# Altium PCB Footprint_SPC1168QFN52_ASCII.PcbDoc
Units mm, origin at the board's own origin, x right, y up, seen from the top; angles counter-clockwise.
Board outline 152.4 x 101.6 mm, 2 copper layers (Top Layer, Bottom Layer); 1 components, 0 nets, 57 pads, 16 vias.
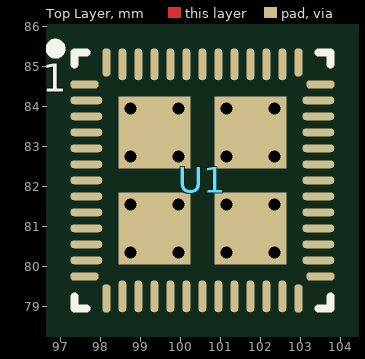
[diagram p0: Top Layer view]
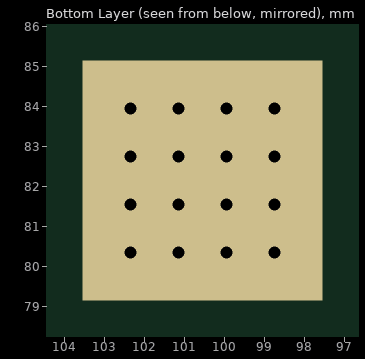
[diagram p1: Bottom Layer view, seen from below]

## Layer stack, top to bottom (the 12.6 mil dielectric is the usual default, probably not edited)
Top Solder: solder mask 0.0102, Solder Resist, Dk 3.5
Top Layer: signal copper 0.0356
Dielectric 1: dielectric 0.32, FR-4, Dk 4.8
Bottom Layer: signal copper 0.0356
Bottom Solder: solder mask 0.0102, Solder Resist, Dk 3.5

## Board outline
25.4,25.4 177.8,25.4 177.8,127 25.4,127

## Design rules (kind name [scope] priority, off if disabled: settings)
AssemblyTestPointUsage [All] p0: scope1count=1 scope1_0_kind=Board scope1_0_value=Board scope2count=1 scope2_0_kind=Board scope2_0_value=Board commentlength=0
AssemblyTestpoint [All] p0: scope1count=1 scope1_0_kind=Board scope1_0_value=Board scope2count=1 scope2_0_kind=Board scope2_0_value=Board commentlength=0
Clearance [All] p0: scope1count=1 scope1_0_kind=Board scope1_0_value=Board scope2count=1 scope2_0_kind=Board scope2_0_value=Board commentlength=0 gap=0.254
Clearance [All] p1: gap=0.254 ignorepadtopadclearanceinfootprint=FALSE except(0: Arc-Hole Track-Hole SMDPad-Hole THPad-Hole Via-Hole Fill-Hole Poly-Hole Region-Hole Text-Hole)
ComponentClearance [All] p0: scope1count=1 scope1_0_kind=Board scope1_0_value=Board scope2count=1 scope2_0_kind=Board scope2_0_value=Board commentlength=0 gap=0.254 collisioncheckmode=3
DiffPairsRouting [All] p0: scope1count=1 scope1_0_kind=Board scope1_0_value=Board scope2count=1 scope2_0_kind=Board scope2_0_value=Board commentlength=0
FabricationTestPointUsage [All] p0: scope1count=1 scope1_0_kind=Board scope1_0_value=Board scope2count=1 scope2_0_kind=Board scope2_0_value=Board commentlength=0 valid=0 allowmultiple=FALSE
FabricationTestpoint [All] p0: scope1count=1 scope1_0_kind=Board scope1_0_value=Board scope2count=1 scope2_0_kind=Board scope2_0_value=Board commentlength=0 side=3 testpointundercomponent=TRUE minsize=1.016 maxsize=2.54 preferedsize=1.524 minholesize=0 maxholesize=1.016 preferedholesize=0.813 testpointgrid=0.025
FanoutControl Fanout_BGA [All] p0 off: scope1count=1 scope1_0_kind=Board scope1_0_value=Board scope2count=1 scope2_0_kind=Board scope2_0_value=Board commentlength=69 // Protel DXP Scope 1 Expression Was: IsBGA   Fanout_BGA (Default Rule)
FanoutControl Fanout_LCC [All] p0 off: scope1count=1 scope1_0_kind=Board scope1_0_value=Board scope2count=1 scope2_0_kind=Board scope2_0_value=Board commentlength=69 // Protel DXP Scope 1 Expression Was: IsLCC   Fanout_LCC (Default Rule)
FanoutControl Fanout_SOIC [All] p0 off: scope1count=1 scope1_0_kind=Board scope1_0_value=Board scope2count=1 scope2_0_kind=Board scope2_0_value=Board commentlength=71 // Protel DXP Scope 1 Expression Was: IsSOIC   Fanout_SOIC (Default Rule)
FanoutControl Fanout_Small [All] p0 off: scope1count=1 scope1_0_kind=Board scope1_0_value=Board scope2count=1 scope2_0_kind=Board scope2_0_value=Board commentlength=84 // Protel DXP Scope 1 Expression Was: (CompPinCount < 5)   Fanout_Small (Default Rule)
FanoutControl Fanout_Default [All] p0: scope1count=1 scope1_0_kind=Board scope1_0_value=Board scope2count=1 scope2_0_kind=Board scope2_0_value=Board commentlength=30 // Fanout_Default (Default Rule)
Height [All] p0: scope1count=1 scope1_0_kind=Board scope1_0_value=Board scope2count=1 scope2_0_kind=Board scope2_0_value=Board commentlength=0
HoleSize [All] p0: scope1count=1 scope1_0_kind=Board scope1_0_value=Board scope2count=1 scope2_0_kind=Board scope2_0_value=Board commentlength=0 absolutevalues=TRUE maxlimit=2.54 minlimit=0.025 maxpercent=80.000 minpercent=20.000
HoleToHoleClearance [All] p0: scope1count=1 scope1_0_kind=Board scope1_0_value=Board scope2count=1 scope2_0_kind=Board scope2_0_value=Board commentlength=0
LayerPairs [All] p0: scope1count=1 scope1_0_kind=Board scope1_0_value=Board scope2count=1 scope2_0_kind=Board scope2_0_value=Board commentlength=0 enforce=TRUE
MinimumSolderMaskSliver [All] p0: scope1count=1 scope1_0_kind=Board scope1_0_value=Board scope2count=1 scope2_0_kind=Board scope2_0_value=Board commentlength=0
NetAntennae [All] p0: scope1count=1 scope1_0_kind=Board scope1_0_value=Board scope2count=1 scope2_0_kind=Board scope2_0_value=Board commentlength=0
PasteMaskExpansion [All] p0: scope1count=1 scope1_0_kind=Board scope1_0_value=Board scope2count=1 scope2_0_kind=Board scope2_0_value=Board commentlength=0 expansion=0
PlaneClearance [All] p0: scope1count=1 scope1_0_kind=Board scope1_0_value=Board scope2count=1 scope2_0_kind=Board scope2_0_value=Board commentlength=0 clearance=0.508
PlaneConnect [All] p0: scope1count=1 scope1_0_kind=Board scope1_0_value=Board scope2count=1 scope2_0_kind=Board scope2_0_value=Board commentlength=0 planeconnectstyle=Relief reliefexpansion=0.508 reliefentries=4 reliefconductorwidth=0.254 reliefairgap=0.254
PolygonConnect [All] p0: scope1count=1 scope1_0_kind=Board scope1_0_value=Board scope2count=1 scope2_0_kind=Board scope2_0_value=Board commentlength=0 connectstyle=Relief reliefconductorwidth=0.254 reliefentries=4 polygonreliefangle="90 Angle"
PolygonConnect [All] p1: connectstyle=Relief reliefconductorwidth=0.254 reliefentries=4 polygonreliefangle="90 Angle" airgapwidth=0.254
RoutingCorners [All] p0: scope1count=1 scope1_0_kind=Board scope1_0_value=Board scope2count=1 scope2_0_kind=Board scope2_0_value=Board commentlength=0 cornerstyle=45-Degree minsetback=2.54 maxsetback=2.54
RoutingLayers [All] p0: scope1count=1 scope1_0_kind=Board scope1_0_value=Board scope2count=1 scope2_0_kind=Board scope2_0_value=Board commentlength=0 top layer=Automatic bottom layer=Automatic
RoutingPriority [All] p0: scope1count=1 scope1_0_kind=Board scope1_0_value=Board scope2count=1 scope2_0_kind=Board scope2_0_value=Board commentlength=0
RoutingTopology [All] p0: scope1count=1 scope1_0_kind=Board scope1_0_value=Board scope2count=1 scope2_0_kind=Board scope2_0_value=Board commentlength=0 topology=Shortest
RoutingVias [All] p0: scope1count=1 scope1_0_kind=Board scope1_0_value=Board scope2count=1 scope2_0_kind=Board scope2_0_value=Board commentlength=0 holewidth=0.711 width=1.27 viastyle="Through Hole" minholewidth=0.711 minwidth=1.27 maxholewidth=0.711 maxwidth=1.27
RoutingVias [All] p1: holewidth=0.711 width=1.27 viastyle="Through Hole" minholewidth=0.711 minwidth=1.27 maxholewidth=0.711 maxwidth=1.27
ShortCircuit [All] p0: scope1count=1 scope1_0_kind=Board scope1_0_value=Board scope2count=1 scope2_0_kind=Board scope2_0_value=Board commentlength=0 allowed=FALSE
SilkToBoardRegionClearance [All] p0: scope1count=1 scope1_0_kind=Board scope1_0_value=Board scope2count=1 scope2_0_kind=Board scope2_0_value=Board commentlength=0
SilkToSilkClearance [All] p0: scope1count=1 scope1_0_kind=Board scope1_0_value=Board scope2count=1 scope2_0_kind=Board scope2_0_value=Board commentlength=0
SilkToSolderMaskClearance [All] p0 off: scope1count=1 scope1_0_kind=Board scope1_0_value=Board scope2count=1 scope2_0_kind=Board scope2_0_value=Board commentlength=44 // Protel DXP Scope 1 Expression Was: IsPad
SolderMaskExpansion [All] p0: scope1count=1 scope1_0_kind=Board scope1_0_value=Board scope2count=1 scope2_0_kind=Board scope2_0_value=Board commentlength=0 expansion=0.102
SolderMaskExpansion [All] p1: expansion=0.102 istentingtop=FALSE
UnRoutedNet [All] p0: scope1count=1 scope1_0_kind=Board scope1_0_value=Board scope2count=1 scope2_0_kind=Board scope2_0_value=Board commentlength=0
UnpouredPolygon [All] p0: scope1count=1 scope1_0_kind=Board scope1_0_value=Board scope2count=1 scope2_0_kind=Board scope2_0_value=Board commentlength=0
Width [All] p0: scope1count=1 scope1_0_kind=Board scope1_0_value=Board scope2count=1 scope2_0_kind=Board scope2_0_value=Board commentlength=0 maxlimit=0.254 minlimit=0.254 preferedwidth=0.254
Width [All] p1: maxlimit=0.254 minlimit=0.254 preferedwidth=0.254
30 further rules are at their usual default settings.

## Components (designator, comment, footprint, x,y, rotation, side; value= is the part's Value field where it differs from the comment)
U1 "" QFN-52-0.4 99.356,83.352 r0 top

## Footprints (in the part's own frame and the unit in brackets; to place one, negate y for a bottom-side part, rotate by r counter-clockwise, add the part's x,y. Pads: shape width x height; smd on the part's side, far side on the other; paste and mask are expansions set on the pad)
QFN-52-0.4 [mm] "P0.4,6*6mm"
  rect 1.8x1.8 smd: 0(0,-2.4) 0(0,0) 0(2.4,-2.4) 0(2.4,0)
  rect 6x6 smd far side: 0(1.2,-1.2)
  oct 0.7x0.2 smd: 1(-1.75,1.2) 13(-1.75,-3.6) 27(4.15,-3.6) 39(4.15,1.2)
  oval 0.8x0.2 smd: 2(-1.7,0.8) 3(-1.7,0.4) 4(-1.7,0) 5(-1.7,-0.4) 6(-1.7,-0.8) 7(-1.7,-1.2) 8(-1.7,-1.6) 9(-1.7,-2) 10(-1.7,-2.4) 11(-1.7,-2.8) 12(-1.7,-3.2) 28(4.1,-3.2) 29(4.1,-2.8) 30(4.1,-2.4) 31(4.1,-2) 32(4.1,-1.6) 33(4.1,-1.2) 34(4.1,-0.8) 35(4.1,-0.4) 36(4.1,0) 37(4.1,0.4) 38(4.1,0.8)
  oct 0.2x0.7 smd: 14(-1.2,-4.15) 26(3.6,-4.15) 40(3.6,1.75) 52(-1.2,1.75)
  oval 0.2x0.8 smd: 15(-0.8,-4.1) 16(-0.4,-4.1) 17(0,-4.1) 18(0.4,-4.1) 19(0.8,-4.1) 20(1.2,-4.1) 21(1.6,-4.1) 22(2,-4.1) 23(2.4,-4.1) 24(2.8,-4.1) 25(3.2,-4.1) 41(3.2,1.7) 42(2.8,1.7) 43(2.4,1.7) 44(2,1.7) 45(1.6,1.7) 46(1.2,1.7) 47(0.8,1.7) 48(0.4,1.7) 49(0,1.7) 50(-0.4,1.7) 51(-0.8,1.7)
  silkscreen extent -2.59,-4.4 4.4,2.21

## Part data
U1: library part SPC1168QFN52

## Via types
v1: diameter 0.6, hole 0.3, Top Layer to Bottom Layer, 16 vias

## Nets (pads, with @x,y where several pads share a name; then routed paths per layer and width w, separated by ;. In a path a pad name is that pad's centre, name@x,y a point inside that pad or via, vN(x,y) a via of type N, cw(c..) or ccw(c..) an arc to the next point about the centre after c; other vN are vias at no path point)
pads on no net: U1.0 U1.1 U1.2 U1.3 U1.4 U1.5 U1.6 U1.7 U1.8 U1.9 U1.10 U1.11 U1.12 U1.13 U1.14 U1.15 U1.16 U1.17 U1.18 U1.19 U1.20 U1.21 U1.22 U1.23 U1.24 U1.25 U1.26 U1.27 U1.28 U1.29 U1.30 U1.31 U1.32 U1.33 U1.34 U1.35 U1.36 U1.37 U1.38 U1.39 U1.40 U1.41 U1.42 U1.43 U1.44 U1.45 U1.46 U1.47 U1.48 U1.49 U1.50 U1.51 U1.52
copper on no net:
  other v1: 98.756,80.352 99.956,80.352 101.156,80.352 102.356,80.352 98.756,81.552 99.956,81.552 101.156,81.552 102.356,81.552 98.756,82.752 99.956,82.752 101.156,82.752 102.356,82.752 98.756,83.952 99.956,83.952 101.156,83.952 102.356,83.952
